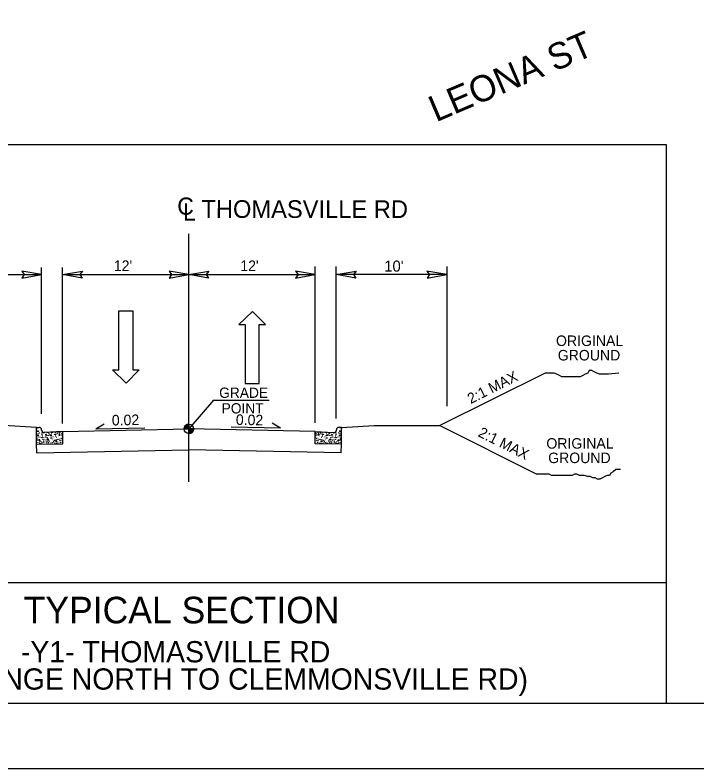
# Model space of a CAD drawing. Extents: x 1636954 to 1644154, y 841334 to 845582.
# Drawn here: x 1641083 to 1641603, y 841334 to 841909 of the extents above; entities that cross this region are included whole.
import ezdxf

# ---------------------------------------------------------------- set-up
doc = ezdxf.new("R2010")
doc.units = 0
for name, color, linetype in [('Exist Roads EOT Text', 7, 'Continuous'), ('Prop Dimension', 7, 'Continuous'), ('Prop Lane Lines', 7, 'Continuous'), ('Prop PHM Legend CELL', 7, 'Continuous'), ('Scratch_Level_1', 7, 'Continuous'), ('Sheet Plan And Profile CELL', 7, 'Continuous'), ('Typical Curb CELL', 7, 'Continuous'), ('Typical Grade Point Symbol CELL', 7, 'Continuous'), ('Typical Hinge Slope Arterial CELL', 7, 'Continuous'), ('Typical Hinge Slope Interstate CELL', 7, 'Continuous'), ('Typical Pavement Slope CELL', 7, 'Continuous'), ('Typical Pavement Slope Information CELL', 7, 'Continuous'), ('Typical Shoulder Slope CELL', 7, 'Continuous'), ('Typical Text Centerline CELL', 7, 'Continuous'), ('Typical Text General CELL', 7, 'Continuous'), ('Typical Text Grade Point CELL', 7, 'Continuous'), ('Typical Text Label CELL', 7, 'Continuous')]:
    doc.layers.add(name, color=color, linetype=linetype)

msp = doc.modelspace()

# ---------------------------------------------------------------- linework, layer by layer
at = {"layer": 'Prop Dimension'}
for p, q in [((1641103.5, 841604.85), (1641103.5, 841716.45)), ((1641119.51, 841597.28), (1641119.51, 841716.45)), ((1641312.21, 841597.9), (1641312.21, 841717.07)), ((1641328.08, 841601.3), (1641328.2, 841717.06)), ((1641412.46, 841716.97), (1641412.36, 841610.67)), ((1641019.13, 841710.89), (1641103.5, 841710.89)), ((1641119.51, 841710.89), (1641215.77, 841710.89)), ((1641215.77, 841710.9), (1641312.21, 841710.9)), ((1641412.46, 841710.89), (1641328.19, 841710.89)), ((1641162.46, 841638.29), (1641162.46, 841683.18)), ((1641162.46, 841683.18), (1641173.04, 841683.18)), ((1641173.04, 841683.18), (1641173.04, 841638.29)), ((1641264.23, 841682.9), (1641253.97, 841672.8)), ((1641274.17, 841672.8), (1641264.23, 841682.9)), ((1641253.97, 841672.8), (1641258.78, 841672.8)), ((1641258.78, 841672.8), (1641258.78, 841627.91)), ((1641269.36, 841627.91), (1641269.36, 841672.8)), ((1641269.36, 841672.8), (1641274.17, 841672.8)), ((1641167.91, 841628.19), (1641157.65, 841638.29)), ((1641157.65, 841638.29), (1641162.46, 841638.29)), ((1641177.85, 841638.29), (1641167.91, 841628.19)), ((1641173.04, 841638.29), (1641177.85, 841638.29)), ((1641258.78, 841627.91), (1641269.36, 841627.91))]:
    msp.add_line(p, q, dxfattribs=at)
for points in [[(1641088.47, 841708.3), (1641103.5, 841710.89), (1641088.39, 841713.56), (1641090.31, 841710.89)], [(1641134.55, 841708.3), (1641119.51, 841710.89), (1641134.63, 841713.56), (1641132.71, 841710.89)], [(1641200.74, 841708.3), (1641215.77, 841710.89), (1641200.66, 841713.56), (1641202.58, 841710.89)], [(1641230.81, 841708.31), (1641215.77, 841710.9), (1641230.89, 841713.57), (1641228.97, 841710.9)], [(1641297.17, 841708.31), (1641312.21, 841710.9), (1641297.09, 841713.57), (1641299.01, 841710.9)], [(1641343.22, 841708.3), (1641328.19, 841710.89), (1641343.31, 841713.56), (1641341.39, 841710.89)], [(1641397.42, 841708.3), (1641412.46, 841710.89), (1641397.34, 841713.56), (1641399.26, 841710.89)]]:
    msp.add_lwpolyline(points, close=True, dxfattribs=at)
at = {"layer": 'Prop PHM Legend CELL'}
msp.add_line((1640851.71, 841475.99), (1641579.63, 841475.99), dxfattribs=at)
msp.add_lwpolyline([(1640851.71, 841810.2), (1641579.63, 841810.2), (1641579.63, 841383.94), (1640851.71, 841383.94)], close=True, dxfattribs=at)
at = {"layer": 'Scratch_Level_1'}
msp.add_lwpolyline([(1636954.2, 841333.94), (1636954.2, 844733.94), (1644154.2, 844733.94), (1644154.2, 841333.94)], close=True, dxfattribs=at)
at = {"layer": 'Sheet Plan And Profile CELL'}
msp.add_lwpolyline([(1637004.2, 841383.94), (1637004.2, 844683.94), (1644104.2, 844683.94), (1644104.2, 841383.94)], close=True, dxfattribs=at)
at = {"layer": 'Typical Curb CELL'}
for p, q in [((1641099.49, 841594.34), (1641101.58, 841594.37)), ((1641099.69, 841581.56), (1641099.49, 841594.34)), ((1641332.29, 841594.34), (1641330.21, 841594.37)), ((1641332.1, 841581.56), (1641332.29, 841594.34)), ((1641099.83, 841591.32), (1641101.06, 841591.69)), ((1641100.94, 841590.97), (1641099.83, 841591.32)), ((1641100.88, 841588.78), (1641100.06, 841588.16)), ((1641100.06, 841588.16), (1641101.39, 841587.87)), ((1641101.39, 841587.87), (1641100.88, 841588.78)), ((1641101.06, 841591.69), (1641100.94, 841590.97)), ((1641103.53, 841592.4), (1641103.53, 841592.48)), ((1641119.58, 841591.31), (1641105.56, 841590.51)), ((1641106.82, 841589.32), (1641106.55, 841588.41)), ((1641106.55, 841588.41), (1641107.52, 841588.37)), ((1641107.52, 841588.37), (1641106.82, 841589.32)), ((1641110.89, 841588.93), (1641110.07, 841588.32)), ((1641110.07, 841588.32), (1641111.4, 841588.02)), ((1641111.4, 841588.02), (1641110.89, 841588.93)), ((1641116.82, 841589.47), (1641116.56, 841588.56)), ((1641116.56, 841588.56), (1641117.53, 841588.52)), ((1641117.53, 841588.52), (1641116.82, 841589.47)), ((1641119.72, 841581.96), (1641119.58, 841591.31)), ((1641312.07, 841581.96), (1641312.21, 841591.31)), ((1641312.21, 841591.31), (1641326.23, 841590.51)), ((1641314.25, 841588.52), (1641314.96, 841589.47)), ((1641315.22, 841588.55), (1641314.25, 841588.52)), ((1641314.96, 841589.47), (1641315.22, 841588.55)), ((1641320.38, 841588.02), (1641320.9, 841588.93)), ((1641321.71, 841588.31), (1641320.38, 841588.02)), ((1641320.9, 841588.93), (1641321.71, 841588.31)), ((1641324.27, 841588.37), (1641324.97, 841589.31)), ((1641325.23, 841588.4), (1641324.27, 841588.37)), ((1641324.97, 841589.31), (1641325.23, 841588.4)), ((1641328.26, 841592.39), (1641328.26, 841592.48)), ((1641330.39, 841587.86), (1641330.91, 841588.77)), ((1641331.72, 841588.16), (1641330.39, 841587.86)), ((1641330.73, 841591.69), (1641330.85, 841590.96)), ((1641331.96, 841591.31), (1641330.73, 841591.69)), ((1641330.85, 841590.96), (1641331.96, 841591.31)), ((1641330.91, 841588.77), (1641331.72, 841588.16)), ((1641099.69, 841581.56), (1641119.72, 841581.96)), ((1641101.95, 841585.17), (1641101.13, 841584.56)), ((1641101.13, 841584.56), (1641102.46, 841584.26)), ((1641102.46, 841584.26), (1641101.95, 841585.17)), ((1641108.41, 841585.63), (1641107.59, 841585.01)), ((1641107.59, 841585.01), (1641108.92, 841584.71)), ((1641108.92, 841584.71), (1641108.41, 841585.63)), ((1641114.87, 841584.27), (1641114.05, 841583.66)), ((1641114.05, 841583.66), (1641115.39, 841583.36)), ((1641115.39, 841583.36), (1641114.87, 841584.27)), ((1641332.1, 841581.56), (1641312.07, 841581.96)), ((1641316.4, 841583.36), (1641316.91, 841584.27)), ((1641317.73, 841583.65), (1641316.4, 841583.36)), ((1641316.91, 841584.27), (1641317.73, 841583.65)), ((1641322.86, 841584.71), (1641323.38, 841585.62)), ((1641324.19, 841585.01), (1641322.86, 841584.71)), ((1641323.38, 841585.62), (1641324.19, 841585.01)), ((1641329.32, 841584.26), (1641329.84, 841585.17)), ((1641330.66, 841584.56), (1641329.32, 841584.26)), ((1641329.84, 841585.17), (1641330.66, 841584.56))]:
    msp.add_line(p, q, dxfattribs=at)
for centre in [(1641099.61, 841593.46), (1641101.35, 841593.76), (1641330.44, 841593.76), (1641332.17, 841593.46), (1641100.05, 841592), (1641100.86, 841589.83), (1641101.81, 841590.25), (1641103.25, 841588.95), (1641103.87, 841590.51), (1641104.01, 841587.5), (1641104.01, 841590.11), (1641104.26, 841588.74), (1641105.44, 841589.44), (1641105.66, 841590.26), (1641107.22, 841589.97), (1641107.99, 841590.41), (1641108.25, 841588.39), (1641108.87, 841589.68), (1641109.02, 841588.03), (1641109.31, 841589.96), (1641109.46, 841589.18), (1641110.87, 841589.98), (1641111.82, 841590.4), (1641112.15, 841587.21), (1641113.26, 841589.1), (1641113.88, 841590.66), (1641114.02, 841587.65), (1641114.02, 841590.26), (1641114.27, 841588.89), (1641115.45, 841589.59), (1641115.67, 841590.41), (1641116.59, 841587.19), (1641116.85, 841590.94), (1641117.23, 841590.12), (1641118, 841590.82), (1641118.26, 841588.54), (1641118.88, 841589.83), (1641119.03, 841588.18), (1641119.33, 841590.11), (1641119.47, 841589.34), (1641312.31, 841589.33), (1641312.46, 841590.11), (1641312.75, 841588.18), (1641312.9, 841589.83), (1641313.53, 841588.53), (1641313.79, 841590.81), (1641314.56, 841590.12), (1641314.94, 841590.93), (1641315.2, 841587.18), (1641316.12, 841590.41), (1641316.33, 841589.59), (1641317.51, 841588.88), (1641317.76, 841590.25), (1641317.77, 841587.65), (1641317.91, 841590.66), (1641318.52, 841589.1), (1641319.64, 841587.21), (1641319.96, 841590.4), (1641320.92, 841589.98), (1641322.32, 841589.18), (1641322.47, 841589.95), (1641322.76, 841588.03), (1641322.92, 841589.67), (1641323.54, 841588.38), (1641323.8, 841590.41), (1641324.57, 841589.97), (1641326.13, 841590.26), (1641326.34, 841589.44), (1641327.52, 841588.73), (1641327.77, 841590.1), (1641327.78, 841587.49), (1641327.92, 841590.5), (1641328.53, 841588.94), (1641329.97, 841590.24), (1641330.93, 841589.82), (1641331.74, 841592), (1641100.08, 841584.27), (1641100.52, 841585.43), (1641100.61, 841582.95), (1641100.77, 841586.71), (1641101.84, 841583.11), (1641102.14, 841587.06), (1641102.21, 841582.22), (1641103.21, 841583.45), (1641103.56, 841586.57), (1641103.58, 841582.47), (1641104.32, 841585.35), (1641104.63, 841582.97), (1641104.93, 841586.82), (1641105.08, 841583.89), (1641105.33, 841585.13), (1641106, 841583.22), (1641106.54, 841584.72), (1641106.58, 841587.03), (1641106.98, 841585.88), (1641107.07, 841583.41), (1641107.47, 841582.44), (1641107.86, 841586.5), (1641108.3, 841583.56), (1641108.84, 841582.69), (1641109.55, 841586.71), (1641109.67, 841583.9), (1641110.55, 841582.44), (1641110.78, 841586.87), (1641110.78, 841585.8), (1641111.09, 841583.42), (1641111.54, 841584.34), (1641111.79, 841585.58), (1641111.92, 841582.69), (1641112.46, 841583.67), (1641113.01, 841583.37), (1641113.45, 841584.52), (1641113.53, 841582.05), (1641113.57, 841586.73), (1641114.68, 841585.07), (1641114.76, 841582.21), (1641114.94, 841586.98), (1641116.05, 841585.32), (1641116.13, 841582.55), (1641117.24, 841584.44), (1641117.39, 841585.6), (1641117.56, 841582.07), (1641117.88, 841586.66), (1641118, 841582.99), (1641118.25, 841584.23), (1641118.76, 841585.85), (1641118.93, 841582.32), (1641119.56, 841586.87), (1641312.23, 841586.86), (1641312.86, 841582.31), (1641313.03, 841585.84), (1641313.53, 841584.23), (1641313.79, 841582.99), (1641313.91, 841586.65), (1641314.23, 841582.06), (1641314.4, 841585.59), (1641314.54, 841584.44), (1641315.66, 841582.55), (1641315.73, 841585.32), (1641316.84, 841586.97), (1641317.02, 841582.21), (1641317.1, 841585.07), (1641318.21, 841586.72), (1641318.26, 841582.05), (1641318.34, 841584.52), (1641318.78, 841583.37), (1641319.32, 841583.67), (1641319.86, 841582.69), (1641319.99, 841585.58), (1641320.25, 841584.34), (1641320.69, 841583.42), (1641321, 841586.86), (1641321, 841585.79), (1641321.23, 841582.44), (1641322.12, 841583.9), (1641322.24, 841586.71), (1641322.95, 841582.69), (1641323.48, 841583.56), (1641323.92, 841586.5), (1641324.32, 841582.44), (1641324.72, 841583.4), (1641324.8, 841585.87), (1641325.21, 841587.03), (1641325.24, 841584.72), (1641325.78, 841583.22), (1641326.46, 841585.13), (1641326.71, 841583.89), (1641326.85, 841586.82), (1641327.15, 841582.97), (1641327.47, 841585.34), (1641328.21, 841582.46), (1641328.22, 841586.57), (1641328.58, 841583.45), (1641329.58, 841582.21), (1641329.65, 841587.05), (1641329.95, 841583.11), (1641331.02, 841586.71), (1641331.18, 841582.95), (1641331.26, 841585.42), (1641331.7, 841584.27)]:
    msp.add_circle(centre, 0.0643, dxfattribs=at)
for centre, start, end in [((1641101.61, 841592.45), 0.8814, 90.8814), ((1641330.18, 841592.45), 89.1186, 179.1186), ((1641105.45, 841592.43), 180.8814, 273.26586), ((1641326.34, 841592.42), 266.73414, 359.1186)]:
    msp.add_arc(centre, 1.92, start, end, dxfattribs=at)
at = {"layer": 'Typical Grade Point Symbol CELL'}
for p, q in [((1641212.19, 841593.24), (1641215.77, 841593.24)), ((1641215.77, 841593.24), (1641215.77, 841596.82)), ((1641215.78, 841589.65), (1641215.77, 841593.24)), ((1641219.36, 841593.24), (1641215.77, 841593.24)), ((1641215.77, 841593.24), (1641215.78, 841589.65))]:
    msp.add_line(p, q, dxfattribs=at)
for points in [[(1641212.23, 841593.75), (1641212.23, 841593.24)], [(1641212.3, 841594.11), (1641212.3, 841593.24)], [(1641212.37, 841594.36), (1641212.37, 841593.24)], [(1641212.44, 841594.56), (1641212.44, 841593.24)], [(1641212.51, 841594.73), (1641212.51, 841593.24)], [(1641212.59, 841594.88), (1641212.59, 841593.24)], [(1641212.66, 841595.01), (1641212.66, 841593.24)], [(1641212.73, 841595.12), (1641212.73, 841593.24)], [(1641212.8, 841595.24), (1641212.8, 841593.24)], [(1641212.87, 841595.34), (1641212.87, 841593.24)], [(1641212.94, 841595.44), (1641212.94, 841593.24)], [(1641213.02, 841595.52), (1641213.02, 841593.24)], [(1641213.09, 841595.61), (1641213.09, 841593.24)], [(1641213.16, 841595.69), (1641213.16, 841593.24)], [(1641213.23, 841595.76), (1641213.23, 841593.24)], [(1641213.3, 841595.83), (1641213.3, 841593.24)], [(1641213.37, 841595.9), (1641213.37, 841593.24)], [(1641213.45, 841595.96), (1641213.45, 841593.24)], [(1641213.52, 841596.03), (1641213.52, 841593.24)], [(1641213.59, 841596.08), (1641213.59, 841593.24)], [(1641213.66, 841596.13), (1641213.66, 841593.24)], [(1641213.73, 841596.18), (1641213.73, 841593.24)], [(1641213.81, 841596.23), (1641213.81, 841593.24)], [(1641213.88, 841596.28), (1641213.88, 841593.24)], [(1641213.95, 841596.32), (1641213.95, 841593.24)], [(1641214.02, 841596.36), (1641214.02, 841593.24)], [(1641214.09, 841596.4), (1641214.09, 841593.24)], [(1641214.16, 841596.44), (1641214.16, 841593.24)], [(1641214.24, 841596.47), (1641214.24, 841593.24)], [(1641214.31, 841596.5), (1641214.31, 841593.24)], [(1641214.38, 841596.54), (1641214.38, 841593.24)], [(1641214.45, 841596.57), (1641214.45, 841593.24)], [(1641214.52, 841596.6), (1641214.52, 841593.24)], [(1641214.59, 841596.62), (1641214.59, 841593.24)], [(1641214.67, 841596.65), (1641214.67, 841593.24)], [(1641214.74, 841596.67), (1641214.74, 841593.24)], [(1641214.81, 841596.69), (1641214.81, 841593.24)], [(1641214.88, 841596.71), (1641214.88, 841593.24)], [(1641214.95, 841596.73), (1641214.95, 841593.24)], [(1641215.03, 841596.74), (1641215.03, 841593.24)], [(1641215.1, 841596.76), (1641215.1, 841593.24)], [(1641215.17, 841596.78), (1641215.17, 841593.24)], [(1641215.24, 841596.78), (1641215.24, 841593.24)], [(1641215.31, 841596.79), (1641215.31, 841593.24)], [(1641215.38, 841596.8), (1641215.38, 841593.24)], [(1641215.46, 841596.81), (1641215.46, 841593.24)], [(1641215.53, 841596.81), (1641215.53, 841593.24)], [(1641215.6, 841596.81), (1641215.6, 841593.24)], [(1641215.67, 841596.82), (1641215.67, 841593.24)], [(1641215.74, 841596.82), (1641215.74, 841596.82), (1641215.74, 841593.24)], [(1641215.83, 841593.24), (1641215.83, 841589.65), (1641215.83, 841589.65)], [(1641215.9, 841593.24), (1641215.9, 841589.65)], [(1641215.97, 841593.24), (1641215.97, 841589.66)], [(1641216.05, 841593.24), (1641216.05, 841589.66)], [(1641216.12, 841593.24), (1641216.12, 841589.66)], [(1641216.19, 841593.24), (1641216.19, 841589.67)], [(1641216.26, 841593.24), (1641216.26, 841589.68)], [(1641216.33, 841593.24), (1641216.33, 841589.7)], [(1641216.4, 841593.24), (1641216.4, 841589.7)], [(1641216.48, 841593.24), (1641216.48, 841589.72)], [(1641216.55, 841593.24), (1641216.55, 841589.74)], [(1641216.62, 841593.24), (1641216.62, 841589.75)], [(1641216.69, 841593.24), (1641216.69, 841589.77)], [(1641216.76, 841593.24), (1641216.76, 841589.79)], [(1641216.83, 841593.24), (1641216.83, 841589.81)], [(1641216.91, 841593.24), (1641216.91, 841589.83)], [(1641216.98, 841593.24), (1641216.98, 841589.85)], [(1641217.05, 841593.24), (1641217.05, 841589.88)], [(1641217.12, 841593.24), (1641217.12, 841589.91)], [(1641217.19, 841593.24), (1641217.19, 841589.94)], [(1641217.27, 841593.24), (1641217.27, 841589.97)], [(1641217.34, 841593.24), (1641217.34, 841590.01)], [(1641217.41, 841593.24), (1641217.41, 841590.04)], [(1641217.48, 841593.24), (1641217.48, 841590.08)], [(1641217.55, 841593.24), (1641217.55, 841590.12)], [(1641217.62, 841593.24), (1641217.62, 841590.16)], [(1641217.7, 841593.24), (1641217.7, 841590.21)], [(1641217.77, 841593.24), (1641217.77, 841590.25)], [(1641217.84, 841593.24), (1641217.84, 841590.3)], [(1641217.91, 841593.24), (1641217.91, 841590.35)], [(1641217.98, 841593.24), (1641217.98, 841590.4)], [(1641218.05, 841593.24), (1641218.05, 841590.46)], [(1641218.13, 841593.24), (1641218.13, 841590.52)], [(1641218.2, 841593.24), (1641218.2, 841590.59)], [(1641218.27, 841593.24), (1641218.27, 841590.65)], [(1641218.34, 841593.24), (1641218.34, 841590.72)], [(1641218.41, 841593.24), (1641218.41, 841590.8)], [(1641218.49, 841593.24), (1641218.49, 841590.88)], [(1641218.56, 841593.24), (1641218.56, 841590.97)], [(1641218.63, 841593.24), (1641218.63, 841591.06)], [(1641218.7, 841593.24), (1641218.7, 841591.15)], [(1641218.77, 841593.24), (1641218.77, 841591.26)], [(1641218.84, 841593.24), (1641218.84, 841591.37)], [(1641218.92, 841593.24), (1641218.92, 841591.5)], [(1641218.99, 841593.24), (1641218.99, 841591.63)], [(1641219.06, 841593.24), (1641219.06, 841591.78)], [(1641219.13, 841593.24), (1641219.13, 841591.95)], [(1641219.2, 841593.24), (1641219.2, 841592.17)], [(1641219.27, 841593.24), (1641219.27, 841592.42)], [(1641219.35, 841593.24), (1641219.35, 841592.84)]]:
    msp.add_lwpolyline(points, dxfattribs=at)
msp.add_circle((1641215.78, 841593.24), 3.59, dxfattribs=at)
for start, end in [(90.00929, 180.00929), (270.00929, 0.00929)]:
    msp.add_arc((1641215.78, 841593.24), 3.59, start, end, dxfattribs=at)
at = {"layer": 'Typical Hinge Slope Arterial CELL'}
msp.add_lwpolyline([(1641543.71, 841635.85), (1641535.81, 841634.86), (1641533.83, 841634.86), (1641530.87, 841634.86), (1641528.89, 841634.86), (1641526.92, 841635.85), (1641524.94, 841636.84), (1641522.97, 841637.83), (1641520.99, 841637.83), (1641520, 841635.85), (1641518.03, 841634.86), (1641516.05, 841633.87), (1641514.08, 841632.89), (1641512.1, 841632.89), (1641510.13, 841632.89), (1641508.15, 841632.89), (1641506.18, 841632.89), (1641504.2, 841632.89), (1641502.23, 841632.89), (1641500.25, 841632.89), (1641498.28, 841633.87), (1641496.3, 841634.86), (1641494.33, 841635.85), (1641491.36, 841635.85), (1641489.39, 841635.85), (1641487.41, 841635.85)], dxfattribs=at)
at = {"layer": 'Typical Hinge Slope Interstate CELL'}
for p, q in [((1641487.41, 841635.85), (1641407.26, 841595.77)), ((1641407.26, 841595.77), (1641481.19, 841558.68))]:
    msp.add_line(p, q, dxfattribs=at)
msp.add_lwpolyline([(1641544.95, 841562.38), (1641543.1, 841562.38), (1641541.25, 841562.38), (1641539.41, 841560.53), (1641537.56, 841559.6), (1641536.63, 841557.76), (1641534.78, 841557.76), (1641532.94, 841556.84), (1641531.09, 841555.91), (1641529.24, 841554.98), (1641527.39, 841554.98), (1641525.54, 841555.91), (1641523.7, 841555.91), (1641521.85, 841556.84), (1641520, 841556.84), (1641517.23, 841557.76), (1641515.38, 841557.76), (1641513.53, 841557.76), (1641511.68, 841558.68), (1641509.84, 841558.68), (1641507.99, 841557.76), (1641506.14, 841557.76), (1641504.29, 841557.76), (1641502.44, 841557.76), (1641500.6, 841557.76), (1641497.82, 841557.76), (1641495.05, 841557.76), (1641492.28, 841557.76), (1641490.43, 841558.68), (1641487.66, 841558.68), (1641484.89, 841558.68), (1641481.19, 841558.68)], dxfattribs=at)
at = {"layer": 'Typical Pavement Slope CELL'}
for p, q in [((1641119.58, 841591.31), (1641215.77, 841593.24)), ((1641312.21, 841591.31), (1641215.77, 841593.24)), ((1641099.82, 841574.88), (1641099.69, 841581.56)), ((1641331.98, 841574.88), (1641332.1, 841581.56)), ((1641099.82, 841574.88), (1641215.77, 841577.2)), ((1641331.98, 841574.88), (1641215.77, 841577.2))]:
    msp.add_line(p, q, dxfattribs=at)
at = {"layer": 'Typical Pavement Slope Information CELL'}
for p, q in [((1641144.92, 841593.34), (1641151.2, 841597.14)), ((1641144.92, 841593.34), (1641182.3, 841594.09)), ((1641285.54, 841593.79), (1641248.16, 841594.54)), ((1641285.54, 841593.79), (1641279.26, 841597.59))]:
    msp.add_line(p, q, dxfattribs=at)
at = {"layer": 'Typical Shoulder Slope CELL'}
for p, q in [((1641099.49, 841594.34), (1641074.63, 841595.77)), ((1641332.29, 841594.34), (1641357.15, 841595.77)), ((1641357.15, 841595.77), (1641407.26, 841595.77))]:
    msp.add_line(p, q, dxfattribs=at)
at = {"layer": 'Typical Text Centerline CELL'}
msp.add_line((1641215.77, 841552.76), (1641215.77, 841742.07), dxfattribs=at)
at = {"layer": 'Typical Text Grade Point CELL'}
for q in [(1641215.77, 841593.24), (1641277.04, 841615.03)]:
    msp.add_line((1641234.5, 841615.03), q, dxfattribs=at)

# ---------------------------------------------------------------- texts
at = {"layer": 'Exist Roads EOT Text'}
msp.add_text('LEONA ST', height=20, rotation=23.13206, dxfattribs=at).set_placement((1641404.21, 841826.96))
at = {"layer": 'Prop Dimension'}
msp.add_text("10'", height=8.437, rotation=360, dxfattribs=at).set_placement((1641364.79, 841713.16))
at = {"layer": 'Prop Lane Lines'}
for s, p in [('ORIGINAL', (1641495.72, 841656.46)), ('GROUND', (1641497.07, 841645.44)), ('ORIGINAL', (1641488.39, 841578.18)), ('GROUND', (1641489.74, 841567.16))]:
    msp.add_text(s, height=8.016, dxfattribs=at).set_placement(p)
at = {"layer": 'Typical Hinge Slope Interstate CELL'}
for rotation, p in [(26.56458, (1641430.67, 841612.12)), (333.43542, (1641435.73, 841587.89))]:
    msp.add_text('2:1 MAX', height=8.016, rotation=rotation, dxfattribs=at).set_placement(p)
at = {"layer": 'Typical Pavement Slope Information CELL'}
for p in [(1641158.61, 841713.68), (1641255.04, 841713.68)]:
    msp.add_text("12'", height=8.016, dxfattribs=at).set_placement(p)
for rotation, p in [(1.14574, (1641157.14, 841595.83)), (358.85426, (1641251.56, 841596.33))]:
    msp.add_text('0.02', height=8.016, rotation=rotation, dxfattribs=at).set_placement(p)
at = {"layer": 'Typical Text Centerline CELL'}
for s, height, rotation, p in [('C', 13.15, 0.04425, (1641206.91, 841756.55)), ('THOMASVILLE RD', 13.5, 359.94168, (1641225.36, 841754.21)), ('L', 13.15, 359.99115, (1641211.28, 841752.07))]:
    msp.add_text(s, height=height, rotation=rotation, dxfattribs=at).set_placement(p)
at = {"layer": 'Typical Text General CELL'}
for s, p in [('-Y1- THOMASVILLE RD', (1641087.73, 841415.21)), ('(I-40 INTERCHANGE NORTH TO CLEMMONSVILLE RD)', (1640912.27, 841394.41))]:
    msp.add_text(s, height=16.2, dxfattribs=at).set_placement(p)
at = {"layer": 'Typical Text Grade Point CELL'}
for s, p in [('GRADE', (1641238.88, 841616.9)), ('POINT', (1641240.77, 841605.02))]:
    msp.add_text(s, height=7.845, rotation=359.99977, dxfattribs=at).set_placement(p)
at = {"layer": 'Typical Text Label CELL'}
msp.add_text('TYPICAL SECTION', height=20.25, dxfattribs=at).set_placement((1641089.83, 841444.97))

doc.saveas('drawing.dxf')
